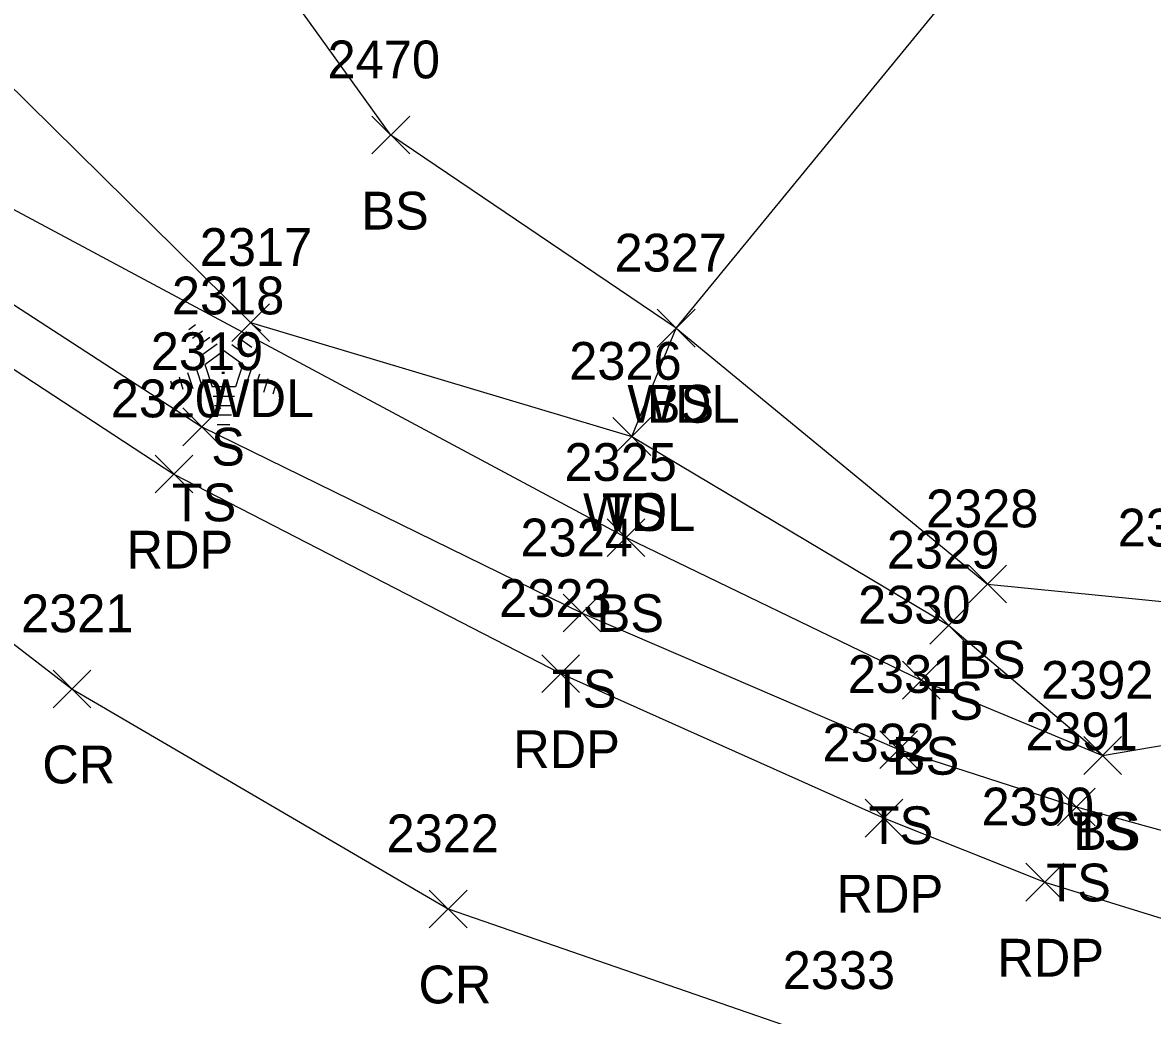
# Model space of a CAD drawing. Extents: x 1461855 to 1464118, y 556196 to 557441.
# Drawn here: x 1462039.2 to 1462099, y 556451.8 to 556504.3 of the extents above; entities that cross this region are included whole.
import ezdxf

# ---------------------------------------------------------------- set-up
doc = ezdxf.new("R2010")
doc.units = 0
for name, color, linetype in [('L_A', 7, 'Continuous'), ('L_I', 7, 'Continuous'), ('L_TIC', 7, 'Continuous'), ('LAWA', 7, 'Continuous'), ('LELB', 7, 'Continuous'), ('LTC', 7, 'Continuous'), ('P_A', 7, 'Continuous'), ('P_I', 7, 'Continuous'), ('P_TIC', 7, 'Continuous'), ('PET', 7, 'Continuous'), ('PRC', 7, 'Continuous')]:
    doc.layers.add(name, color=color, linetype=linetype)

msp = doc.modelspace()

# ---------------------------------------------------------------- linework, layer by layer
at = {"layer": 'L_TIC'}
for points in [[(1462057.724, 556497.395), (1462059.724, 556499.395)], [(1462059.724, 556497.395), (1462057.724, 556499.395)], [(1462050.308, 556487.469), (1462052.308, 556489.469)], [(1462052.308, 556487.469), (1462050.308, 556489.469)], [(1462072.826, 556487.172), (1462074.826, 556489.172)], [(1462074.826, 556487.172), (1462072.826, 556489.172)], [(1462072.826, 556487.172), (1462074.826, 556489.172)], [(1462074.826, 556487.172), (1462072.826, 556489.172)], [(1462072.826, 556487.172), (1462074.826, 556489.172)], [(1462074.826, 556487.172), (1462072.826, 556489.172)], [(1462047.722, 556481.954), (1462049.722, 556483.954)], [(1462049.722, 556481.954), (1462047.722, 556483.954)], [(1462070.482, 556481.443), (1462072.482, 556483.443)], [(1462072.482, 556481.443), (1462070.482, 556483.443)], [(1462070.482, 556481.443), (1462072.482, 556483.443)], [(1462072.482, 556481.443), (1462070.482, 556483.443)], [(1462070.175, 556476.093), (1462072.175, 556478.093)], [(1462072.175, 556476.093), (1462070.175, 556478.093)], [(1462089.308, 556473.634), (1462091.308, 556475.634)], [(1462091.308, 556473.634), (1462089.308, 556475.634)], [(1462067.844, 556472.098), (1462069.844, 556474.098)], [(1462069.844, 556472.098), (1462067.844, 556474.098)], [(1462087.245, 556471.453), (1462089.245, 556473.453)], [(1462089.245, 556471.453), (1462087.245, 556473.453)], [(1462085.801, 556468.546), (1462087.801, 556470.546)], [(1462087.801, 556468.546), (1462085.801, 556470.546)], [(1462084.604, 556464.871), (1462086.604, 556466.871)], [(1462086.604, 556464.871), (1462084.604, 556466.871)], [(1462095.393, 556464.563), (1462097.393, 556466.563)], [(1462097.393, 556464.563), (1462095.393, 556466.563)], [(1462095.393, 556464.563), (1462097.393, 556466.563)], [(1462097.393, 556464.563), (1462095.393, 556466.563)], [(1462094.004, 556461.84), (1462096.004, 556463.84)], [(1462096.004, 556461.84), (1462094.004, 556463.84)]]:
    msp.add_lwpolyline(points, dxfattribs=at)
at = {"layer": 'LAWA'}
msp.add_lwpolyline([(1461966.99, 556643.855), (1461970.758, 556630.806), (1461974.775, 556610.383), (1461978.018, 556594.214), (1461979.63, 556591.534), (1461980.916, 556588.073), (1461980.911, 556585.996), (1461997.991, 556566.696), (1461991.485, 556562.204), (1461998.233, 556546.822), (1462003.925, 556533.351), (1462020.908, 556518.859), (1462035.594, 556503.943), (1462051.308, 556488.469), (1462071.482, 556482.443), (1462073.826, 556488.172), (1462091.483, 556509.713), (1462111.543, 556518.091), (1462114.944, 556522.402), (1462105.835, 556530.217)], dxfattribs=at)
at = {"layer": 'LELB'}
for points in [[(1461963.705, 556606.006), (1461972.105, 556589.426), (1461974.569, 556579.664), (1461977.523, 556575.662), (1461983.683, 556561.117), (1461995.205, 556544.635), (1462001.849, 556531.766), (1462015.715, 556512.95), (1462031.601, 556494.072), (1462048.722, 556482.954), (1462068.844, 556473.098), (1462085.604, 556465.871), (1462095.004, 556462.84), (1462104.945, 556460.104), (1462122.08, 556455.999), (1462130.643, 556454.493), (1462134.696, 556456.084), (1462145.09, 556459.049)], [(1462073.826, 556488.172), (1462058.724, 556498.395), (1462047.72, 556513.704), (1462037.062, 556530.069), (1462022.313, 556535.546), (1462008.95, 556552.393), (1462011.129, 556562.18), (1462015.8, 556575.203), (1462023.416, 556591.583)], [(1462003.925, 556533.351), (1462018.122, 556515.464), (1462033.248, 556497.405), (1462071.175, 556477.093), (1462086.801, 556469.546), (1462096.393, 556465.563), (1462108.839, 556467.675), (1462124.65, 556460.477), (1462134.696, 556456.084)], [(1462073.826, 556488.172), (1462090.308, 556474.634), (1462100.452, 556473.623), (1462115.381, 556476.71), (1462124.684, 556472.395), (1462138.668, 556467.443), (1462145.09, 556459.049), (1462141.891, 556453.801), (1462147.501, 556452.882), (1462151.338, 556453.207)], [(1462071.482, 556482.443), (1462088.245, 556472.453), (1462096.393, 556465.563)]]:
    msp.add_lwpolyline(points, dxfattribs=at)
at = {"layer": 'LTC'}
for p, q in [((1462048.028, 556488.112), (1462048.382, 556488.37)), ((1462051.426, 556488.353), (1462051.845, 556488.048)), ((1462048.237, 556487.647), (1462048.767, 556488.031)), ((1462048.447, 556487.181), (1462049.151, 556487.692)), ((1462050.684, 556487.656), (1462051.363, 556487.162)), ((1462051.055, 556488.004), (1462051.604, 556487.605)), ((1462048.657, 556486.715), (1462049.535, 556487.353)), ((1462050.313, 556487.308), (1462051.122, 556486.719)), ((1462048.881, 556486.26), (1462049.893, 556486.995)), ((1462049.893, 556486.995), (1462050.89, 556486.27)), ((1462048.427, 556486.041), (1462048.757, 556485.022)), ((1462048.881, 556486.26), (1462049.268, 556485.067)), ((1462050.89, 556486.27), (1462050.499, 556485.067)), ((1462051.327, 556485.999), (1462050.989, 556484.959)), ((1462047.06, 556485.391), (1462047.212, 556484.924)), ((1462047.516, 556485.608), (1462047.727, 556484.956)), ((1462047.971, 556485.825), (1462048.242, 556484.989)), ((1462051.772, 556485.749), (1462051.484, 556484.864)), ((1462052.217, 556485.499), (1462051.979, 556484.769)), ((1462052.661, 556485.248), (1462052.474, 556484.674)), ((1462050.499, 556485.067), (1462049.268, 556485.067)), ((1462050.46, 556484.567), (1462049.316, 556484.567)), ((1462050.377, 556484.067), (1462049.388, 556484.067)), ((1462050.293, 556483.567), (1462049.461, 556483.567)), ((1462050.209, 556483.067), (1462049.534, 556483.067))]:
    msp.add_line(p, q, dxfattribs=at)
at = {"layer": 'P_TIC'}
for points in [[(1462046.25, 556479.456), (1462048.25, 556481.456)], [(1462048.25, 556479.456), (1462046.25, 556481.456)], [(1462066.715, 556468.893), (1462068.715, 556470.893)], [(1462068.715, 556468.893), (1462066.715, 556470.893)], [(1462040.849, 556468.086), (1462042.849, 556470.086)], [(1462042.849, 556468.086), (1462040.849, 556470.086)], [(1462083.829, 556461.245), (1462085.829, 556463.245)], [(1462085.829, 556461.245), (1462083.829, 556463.245)], [(1462092.335, 556457.861), (1462094.335, 556459.861)], [(1462094.335, 556457.861), (1462092.335, 556459.861)], [(1462060.758, 556456.443), (1462062.758, 556458.443)], [(1462062.758, 556456.443), (1462060.758, 556458.443)]]:
    msp.add_lwpolyline(points, dxfattribs=at)
at = {"layer": 'PET'}
msp.add_lwpolyline([(1461941.434, 556640.486), (1461960.909, 556600.588), (1461969.587, 556584.051), (1461984.634, 556553.378), (1461998.6, 556528.817), (1462012.322, 556509.397), (1462030.273, 556491.558), (1462047.25, 556480.456), (1462067.715, 556469.893), (1462084.829, 556462.245), (1462093.335, 556458.861), (1462103.997, 556455.555), (1462121.999, 556451.359), (1462134.064, 556450.116), (1462148.835, 556449.192)], dxfattribs=at)
at = {"layer": 'PRC'}
msp.add_lwpolyline([(1461925.455, 556305.981), (1461931.482, 556345.963), (1461937.931, 556386.439), (1461943.124, 556427.083), (1461945.493, 556465.379), (1461946.96, 556493.016), (1461948.287, 556523.837), (1461949.597, 556552.436), (1461949.092, 556575.708), (1461945.132, 556594.535), (1461941.155, 556612.685), (1461941.736, 556618.093), (1461960.038, 556581.267), (1461976.525, 556548.035), (1461990.309, 556523.955), (1462006.117, 556501.89), (1462023.427, 556483.274), (1462041.849, 556469.086), (1462061.758, 556457.443), (1462082.723, 556450.203), (1462107.816, 556443.977), (1462129.573, 556440.387), (1462147.933, 556438.199)], dxfattribs=at)

# ---------------------------------------------------------------- texts
at = {"layer": 'L_A'}
for s, p in [('BS', (1462057.165, 556493.395)), ('WDL', (1462048.725, 556483.469)), ('WDL', (1462071.243, 556483.172)), ('BS', (1462072.267, 556483.172)), ('BS', (1462072.267, 556483.172)), ('S', (1462049.218, 556480.904)), ('TS', (1462047.131, 556477.954)), ('WDL', (1462068.899, 556477.443)), ('TS', (1462069.891, 556477.443)), ('BS', (1462069.616, 556472.093)), ('BS', (1462088.749, 556469.634)), ('TS', (1462067.254, 556468.098)), ('TS', (1462086.654, 556467.453)), ('BS', (1462085.242, 556464.546)), ('TS', (1462084.014, 556460.871)), ('TS', (1462094.802, 556460.563)), ('BS', (1462094.833, 556460.563)), ('TS', (1462093.414, 556457.84))]:
    msp.add_text(s, height=2, dxfattribs=at).set_placement(p)
at = {"layer": 'L_I'}
for s, p in [('2470', (1462055.378, 556501.395)), ('2317', (1462048.615, 556491.469)), ('2327', (1462070.566, 556491.172)), ('2327', (1462070.566, 556491.172)), ('2327', (1462070.566, 556491.172)), ('2318', (1462047.14, 556488.904)), ('2319', (1462046.021, 556485.954)), ('2326', (1462068.167, 556485.443)), ('2326', (1462068.167, 556485.443)), ('2325', (1462067.916, 556480.093)), ('2328', (1462087.048, 556477.634)), ('2324', (1462065.585, 556476.098)), ('2393', (1462097.192, 556476.623)), ('2329', (1462084.977, 556475.453)), ('2330', (1462083.455, 556472.546)), ('2331', (1462082.911, 556468.871)), ('2392', (1462093.133, 556468.563)), ('2392', (1462093.133, 556468.563)), ('2391', (1462092.311, 556465.84))]:
    msp.add_text(s, height=2, dxfattribs=at).set_placement(p)
at = {"layer": 'LTC'}
msp.add_text('.', height=1.037, rotation=270, dxfattribs=at).set_placement((1462049.775, 556486.008))
at = {"layer": 'P_A'}
for s, p in [('RDP', (1462044.739, 556475.456)), ('RDP', (1462065.204, 556464.893)), ('CR', (1462040.282, 556464.086)), ('RDP', (1462082.317, 556457.245)), ('RDP', (1462090.823, 556453.861)), ('CR', (1462060.191, 556452.443))]:
    msp.add_text(s, height=2, dxfattribs=at).set_placement(p)
at = {"layer": 'P_I'}
for s, p in [('2320', (1462043.904, 556483.456)), ('2323', (1462064.456, 556472.893)), ('2321', (1462039.157, 556472.086)), ('2332', (1462081.569, 556465.245)), ('2390', (1462089.989, 556461.861)), ('2322', (1462058.499, 556460.443)), ('2333', (1462079.464, 556453.203))]:
    msp.add_text(s, height=2, dxfattribs=at).set_placement(p)

doc.saveas('drawing.dxf')
